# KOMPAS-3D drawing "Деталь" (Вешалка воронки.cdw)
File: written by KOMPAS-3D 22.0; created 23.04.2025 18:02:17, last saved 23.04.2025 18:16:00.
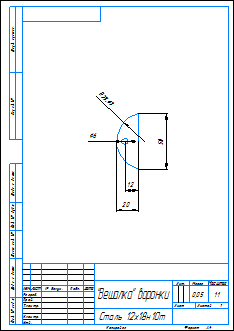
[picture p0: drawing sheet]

Sheet 1: A4, portrait

Document properties: Автор: Admin; Масса: 0.050341; Полное имя файла: Вешалка 1шт.m3d

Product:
- Part/product: Деталь
    Масса: 0.008452

Title block, sheet 1: Наименование: "Вешалка" воронки; Материал: Сталь 12х18н10т; Масса: 0,05; Количество листов документа: 1; Форматы листов документа: A4; stored path: D:\28.11.2016\3D модели\Абилимпикс\2025\Воронка квадратная\Боковина воронки верхняя.cdw

Views: Вид 1, Спереди
Referenced files in D:\28.11.2016\3D модели\Абилимпикс\2025\Воронка квадратная\: Вешалка 1шт.m3d
Dimensions and other numbers on the sheet: 50; 25,63; 6; 12; 20; 1:1; 1; 0,05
